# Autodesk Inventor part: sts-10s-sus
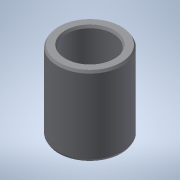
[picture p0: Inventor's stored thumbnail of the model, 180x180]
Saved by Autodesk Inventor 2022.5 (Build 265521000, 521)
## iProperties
Created: 2016-12
Part Number: sts-10s-sus
Material: 一般
Document SubType Name: Modeling
Designer: imaocorp
Density: 1 g/cm^3
Appearance: 既定
Author: imaocorp
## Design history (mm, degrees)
node "sts-10s-sus.x_t1"
node "sts-10s-sus"
node "Base1"
